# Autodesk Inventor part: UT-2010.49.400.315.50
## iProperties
Category: PARTsolutions
Created: 2012-10
Part Number: UT-2010.49.400.315.50
Catalog Web Link: www.cadenas.de
Description: 2010.Unterteil - Unterteil f. SG 2010.
Document SubType Name: Modeling
Designer: PARTsolutions
Density: 1 g/cm^3
NB: UT-2010.49.400.315.50
NN: 2010.Unterteil
NT: Unterteil f. SG 2010.
NBSYN: UT-2010.$PW.$BF..$A1..$B1..$C1.
LINA: UT-2010.49.400.315.50
BF: 9
PW: 4
PK: 1
A1: 400.000
B1: 315.000
LAF: 1
C1: 50
E1: 310.000
D1: 30.000
D2: 32.000
D3: 48.000
E2: 225.000
E3: 270.000
E4: 313.000
C1INHALT: 50
AM: 400.315
KT: X
SUPPLIER: FIBRO
ARTICLENO: UT-2010.49.400.315.50
BOMINFO: UT-2010.49.400.315.50
CREATOR: CADENAS GmbH
PSOL_IDENT_0: {\\10.0.0.251\data_v9\23d-libs\fibro\normalien\a\a02\a02_00\ut_2010_202_19.prj},213 {VTYP=3D},{NB=UT
PSOL_IDENT_1: -2010.49.400.315.50},{LINA=UT-2010.49.400.315.50},{NN=2010.Unterteil},{DATE=10.11.2011 06:58:39},{GE
PSOL_IDENT_2: OMDATE=10.11.2011 06:58:00},{VERSION=v1},{LINEID=180},{LINESUBID=-1},{WBVAR=BF,PW,PK,LAF,C1,AM}  {NB
PSOL_IDENT_3: =UT-2010.49.400.315.50},{LINA=UT-2010.49.400.315.50},{KT=X},{BF=9},{PW=4},{PK=1},{A1=400.000},{B1=31
PSOL_IDENT_4: 5.000},{LAF=1},{C1=50},{E1=310.000},{D1=30.000},{D2=32.000},{D3=48.000},{E2=225.000},{E3=270.000},{E
PSOL_IDENT_5: 4=313.000},{C1INHALT=50},{AM=400.315}
ipwModelExtentsX: 400
ipwModelExtentsY: 50
ipwModelExtentsZ: 315
ipwMass: 6.1
ipwArea: 0.3 m^2
ipwVolume: 6.1
Title: UT-2010.49.400.315.50
Author: Cadenas PARTsolutions
Comments: Unterteil f. SG 2010.
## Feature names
1. Extrusion1
2. Extrusion2
3. Extrusion3
4. Extrusion4
5. Extrusion5
